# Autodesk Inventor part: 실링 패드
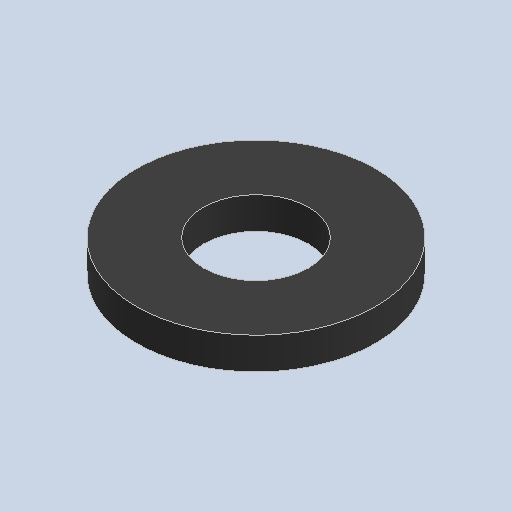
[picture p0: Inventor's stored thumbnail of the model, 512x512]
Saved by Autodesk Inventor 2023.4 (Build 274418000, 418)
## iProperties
Created: 2024-09
Part Number: 실링 패드
Material: 고무
Document SubType Name: Modeling
Designer: EDU
Density: 0.93 g/cm^3
Appearance: 기본값
Author: jhkim
Sending System: Autodesk Inventor 2025
Preprocessor: ST-DEVELOPER v20
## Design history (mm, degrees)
feature "솔리드1"
node "솔리드2"
